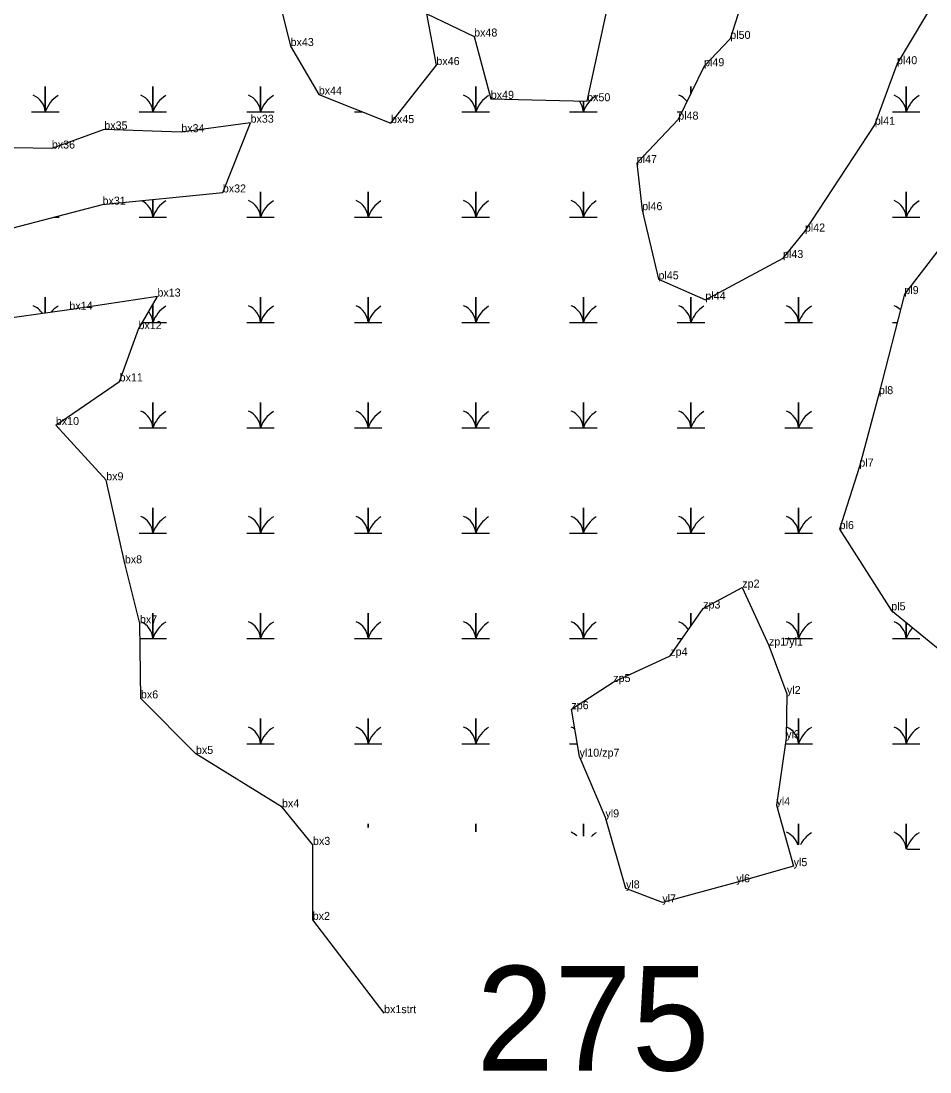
# Model space of a CAD drawing. Extents: x 2072529 to 2268796, y 436423 to 470406.
# Drawn here: x 2233706 to 2234274, y 437646 to 438303 of the extents above; entities that cross this region are included whole.
import ezdxf

# ---------------------------------------------------------------- set-up
doc = ezdxf.new("R2010")
doc.units = 0
for name, color, linetype in [('Default', 7, 'Continuous'), ('Exist Environmental Wetland Boundary', 7, 'Continuous'), ('Exist Environmental Wetland Boundary Cogo Comment', 7, 'Continuous'), ('Exist Hydro Swamp or Marsh', 7, 'Continuous'), ('Old_Level_20', 7, 'Continuous')]:
    doc.layers.add(name, color=color, linetype=linetype)

msp = doc.modelspace()

# ---------------------------------------------------------------- linework, layer by layer
at = {"layer": 'Exist Environmental Wetland Boundary'}
for points in [[(2234206.5, 438606.87), (2234215.25, 438571.96), (2234220.38, 438527.18), (2234204.32, 438480.7), (2234205.77, 438439.37), (2234198.43, 438402.89), (2234171.84, 438403.69), (2234163.55, 438367.07), (2234163.75, 438336.95), (2234149.39, 438291.75), (2234133.01, 438274.68), (2234116.86, 438241.33), (2234090.91, 438214.16), (2234094.32, 438184.72), (2234104.51, 438141.53), (2234133.82, 438128.75), (2234182.34, 438154.84), (2234196, 438171.36), (2234239.71, 438238.05), (2234253.57, 438275.93), (2234280.54, 438321.15)], [(2233858.66, 438351.45), (2233874.62, 438287.27), (2233892.26, 438257), (2233937.37, 438239.13), (2233965.72, 438275.42), (2233959.69, 438307.4), (2233989.31, 438293.23), (2233999.72, 438254.31), (2234059.94, 438252.78), (2234072.76, 438311.45)], [(2233677.19, 438167.39), (2233757.1, 438188.17), (2233832.28, 438195.79), (2233849.59, 438239.38), (2233806.32, 438233.44), (2233758.21, 438235.23), (2233725.42, 438223.22), (2233654.83, 438224.52)], [(2234279.17, 438159.32), (2234258.17, 438132.28), (2234242.26, 438069.78), (2234230.04, 438024.51), (2234217.72, 437985.47), (2234249.98, 437934.73), (2234302.96, 437891.47)], [(2233933.05, 437683.02), (2233888.45, 437741.29), (2233888.62, 437788.17), (2233869.26, 437811.67), (2233815.49, 437844.98), (2233781.11, 437879.68), (2233780.48, 437926.57), (2233771.05, 437964.06), (2233759.41, 438015.96), (2233727.92, 438050.47), (2233767.76, 438077.73), (2233779.58, 438110.39), (2233791.43, 438130.77), (2233736.36, 438122.5), (2233685.39, 438115.35)]]:
    msp.add_lwpolyline(points, dxfattribs=at)
msp.add_lwpolyline([(2234173.58, 437912.73), (2234184.81, 437882.46), (2234184.34, 437854.8), (2234178.23, 437812.94), (2234188.97, 437774.87), (2234153.16, 437764.75), (2234106.93, 437752.24), (2234084.22, 437760.95), (2234071.38, 437805.34), (2234055.2, 437843.29), (2234050.1, 437872.92), (2234076.23, 437889.9), (2234111.89, 437906.38), (2234132.43, 437935.84), (2234156.88, 437948.92)], close=True, dxfattribs=at)
at = {"layer": 'Exist Hydro Swamp or Marsh'}
for points in [[(2233712.73, 438246.13), (2233721.33, 438246.13), (2233721.33, 438261.91), (2233721.33, 438246.13), (2233729.93, 438246.13)], [(2233779.98, 438246.13), (2233788.58, 438246.13), (2233788.58, 438261.91), (2233788.58, 438246.13), (2233797.18, 438246.13)], [(2233847.23, 438246.13), (2233855.83, 438246.13), (2233855.83, 438261.91), (2233855.83, 438246.13), (2233864.43, 438246.13)], [(2233981.73, 438246.13), (2233990.33, 438246.13), (2233990.33, 438261.91), (2233990.33, 438246.13), (2233998.93, 438246.13)], [(2234124.83, 438257.79), (2234124.83, 438261.91), (2234124.83, 438257.79)], [(2234250.73, 438246.13), (2234259.33, 438246.13), (2234259.33, 438261.91), (2234259.33, 438246.13), (2234267.93, 438246.13)], [(2234048.98, 438246.13), (2234057.58, 438246.13), (2234057.58, 438252.84)], [(2234057.58, 438252.84), (2234057.58, 438246.13), (2234066.18, 438246.13)], [(2233914.48, 438246.13), (2233919.7, 438246.13)], [(2234116.23, 438246.13), (2234119.19, 438246.13)], [(2233847.23, 438180.33), (2233855.83, 438180.33), (2233855.83, 438196.11), (2233855.83, 438180.33), (2233864.43, 438180.33)], [(2233914.48, 438180.33), (2233923.08, 438180.33), (2233923.08, 438196.11), (2233923.08, 438180.33), (2233931.68, 438180.33)], [(2233981.73, 438180.33), (2233990.33, 438180.33), (2233990.33, 438196.11), (2233990.33, 438180.33), (2233998.93, 438180.33)], [(2234048.98, 438180.33), (2234057.58, 438180.33), (2234057.58, 438196.11), (2234057.58, 438180.33), (2234066.18, 438180.33)], [(2234250.73, 438180.33), (2234259.33, 438180.33), (2234259.33, 438196.11), (2234259.33, 438180.33), (2234267.93, 438180.33)], [(2233779.98, 438180.33), (2233788.58, 438180.33), (2233788.58, 438191.36)], [(2233788.58, 438191.36), (2233788.58, 438180.33), (2233797.18, 438180.33)], [(2233726.93, 438180.33), (2233729.93, 438180.33)], [(2233721.33, 438120.4), (2233721.33, 438130.31), (2233721.33, 438120.4)], [(2233847.23, 438114.53), (2233855.83, 438114.53), (2233855.83, 438130.31), (2233855.83, 438114.53), (2233864.43, 438114.53)], [(2233914.48, 438114.53), (2233923.08, 438114.53), (2233923.08, 438130.31), (2233923.08, 438114.53), (2233931.68, 438114.53)], [(2233981.73, 438114.53), (2233990.33, 438114.53), (2233990.33, 438130.31), (2233990.33, 438114.53), (2233998.93, 438114.53)], [(2234048.98, 438114.53), (2234057.58, 438114.53), (2234057.58, 438130.31), (2234057.58, 438114.53), (2234066.18, 438114.53)], [(2234116.23, 438114.53), (2234124.83, 438114.53), (2234124.83, 438130.31), (2234124.83, 438114.53), (2234133.43, 438114.53)], [(2234183.48, 438114.53), (2234192.08, 438114.53), (2234192.08, 438130.31), (2234192.08, 438114.53), (2234200.68, 438114.53)], [(2233781.99, 438114.53), (2233788.58, 438114.53), (2233788.58, 438125.87)], [(2233788.58, 438125.87), (2233788.58, 438114.53), (2233797.18, 438114.53)], [(2234250.73, 438114.53), (2234253.65, 438114.53)], [(2233779.98, 438048.73), (2233788.58, 438048.73), (2233788.58, 438064.51), (2233788.58, 438048.73), (2233797.18, 438048.73)], [(2233847.23, 438048.73), (2233855.83, 438048.73), (2233855.83, 438064.51), (2233855.83, 438048.73), (2233864.43, 438048.73)], [(2233914.48, 438048.73), (2233923.08, 438048.73), (2233923.08, 438064.51), (2233923.08, 438048.73), (2233931.68, 438048.73)], [(2233981.73, 438048.73), (2233990.33, 438048.73), (2233990.33, 438064.51), (2233990.33, 438048.73), (2233998.93, 438048.73)], [(2234048.98, 438048.73), (2234057.58, 438048.73), (2234057.58, 438064.51), (2234057.58, 438048.73), (2234066.18, 438048.73)], [(2234116.23, 438048.73), (2234124.83, 438048.73), (2234124.83, 438064.51), (2234124.83, 438048.73), (2234133.43, 438048.73)], [(2234183.48, 438048.73), (2234192.08, 438048.73), (2234192.08, 438064.51), (2234192.08, 438048.73), (2234200.68, 438048.73)], [(2233729.51, 438048.73), (2233729.93, 438048.73)], [(2233779.98, 437982.93), (2233788.58, 437982.93), (2233788.58, 437998.71), (2233788.58, 437982.93), (2233797.18, 437982.93)], [(2233847.23, 437982.93), (2233855.83, 437982.93), (2233855.83, 437998.71), (2233855.83, 437982.93), (2233864.43, 437982.93)], [(2233914.48, 437982.93), (2233923.08, 437982.93), (2233923.08, 437998.71), (2233923.08, 437982.93), (2233931.68, 437982.93)], [(2233981.73, 437982.93), (2233990.33, 437982.93), (2233990.33, 437998.71), (2233990.33, 437982.93), (2233998.93, 437982.93)], [(2234048.98, 437982.93), (2234057.58, 437982.93), (2234057.58, 437998.71), (2234057.58, 437982.93), (2234066.18, 437982.93)], [(2234116.23, 437982.93), (2234124.83, 437982.93), (2234124.83, 437998.71), (2234124.83, 437982.93), (2234133.43, 437982.93)], [(2234183.48, 437982.93), (2234192.08, 437982.93), (2234192.08, 437998.71), (2234192.08, 437982.93), (2234200.68, 437982.93)], [(2233780.61, 437917.13), (2233788.58, 437917.13), (2233788.58, 437932.91), (2233788.58, 437917.13), (2233797.18, 437917.13)], [(2233847.23, 437917.13), (2233855.83, 437917.13), (2233855.83, 437932.91), (2233855.83, 437917.13), (2233864.43, 437917.13)], [(2233914.48, 437917.13), (2233923.08, 437917.13), (2233923.08, 437932.91), (2233923.08, 437917.13), (2233931.68, 437917.13)], [(2233981.73, 437917.13), (2233990.33, 437917.13), (2233990.33, 437932.91), (2233990.33, 437917.13), (2233998.93, 437917.13)], [(2234048.98, 437917.13), (2234057.58, 437917.13), (2234057.58, 437932.91), (2234057.58, 437917.13), (2234066.18, 437917.13)], [(2234124.83, 437924.93), (2234124.83, 437932.91), (2234124.83, 437924.93)], [(2234183.48, 437917.13), (2234192.08, 437917.13), (2234192.08, 437932.91), (2234192.08, 437917.13), (2234200.68, 437917.13)], [(2234250.73, 437917.13), (2234259.33, 437917.13), (2234259.33, 437927.1)], [(2234259.33, 437927.1), (2234259.33, 437917.13), (2234267.93, 437917.13)], [(2234116.23, 437917.13), (2234119.39, 437917.13)], [(2233847.23, 437851.33), (2233855.83, 437851.33), (2233855.83, 437867.11), (2233855.83, 437851.33), (2233864.43, 437851.33)], [(2233914.48, 437851.33), (2233923.08, 437851.33), (2233923.08, 437867.11), (2233923.08, 437851.33), (2233931.68, 437851.33)], [(2233981.73, 437851.33), (2233990.33, 437851.33), (2233990.33, 437867.11), (2233990.33, 437851.33), (2233998.93, 437851.33)], [(2234183.84, 437851.33), (2234192.08, 437851.33), (2234192.08, 437867.11), (2234192.08, 437851.33), (2234200.68, 437851.33)], [(2234250.73, 437851.33), (2234259.33, 437851.33), (2234259.33, 437867.11), (2234259.33, 437851.33), (2234267.93, 437851.33)], [(2234048.98, 437851.33), (2234053.81, 437851.33)], [(2233923.08, 437799.12), (2233923.08, 437801.31), (2233923.08, 437799.12)], [(2233990.33, 437796.41), (2233990.33, 437801.31), (2233990.33, 437796.41)], [(2234057.58, 437793.69), (2234057.58, 437801.31), (2234057.58, 437793.69)], [(2234192.08, 437788.26), (2234192.08, 437801.31), (2234192.08, 437788.26)], [(2234259.33, 437785.55), (2234259.33, 437801.31), (2234259.33, 437785.55)], [(2234259.87, 437785.53), (2234267.93, 437785.53)]]:
    msp.add_lwpolyline(points, dxfattribs=at)
for centre, radius, start, end in [((2233709.06, 438245.24), 12.3, 4.14034, 67.53497), ((2233739.57, 438240.07), 19.22, 122.12745, 161.62219), ((2233776.31, 438245.24), 12.3, 4.14034, 67.53497), ((2233806.82, 438240.07), 19.22, 122.12745, 161.62219), ((2233843.56, 438245.24), 12.3, 4.14034, 67.53497), ((2233874.07, 438240.07), 19.22, 122.12745, 161.62219), ((2233978.06, 438245.24), 12.3, 4.14034, 67.53497), ((2234008.57, 438240.07), 19.22, 122.12745, 161.62219), ((2234075.82, 438240.07), 19.22, 122.12745, 161.62219), ((2234112.56, 438245.24), 12.3, 37.22159, 67.53497), ((2234247.06, 438245.24), 12.3, 4.14034, 67.53497), ((2234277.57, 438240.07), 19.22, 122.12745, 161.62219), ((2234045.31, 438245.24), 12.3, 4.14034, 38.57578), ((2233776.31, 438179.44), 12.3, 4.14034, 65.5639), ((2233806.82, 438174.27), 19.22, 122.12745, 161.62219), ((2233843.56, 438179.44), 12.3, 4.14034, 67.53497), ((2233874.07, 438174.27), 19.22, 122.12745, 161.62219), ((2233910.81, 438179.44), 12.3, 4.14034, 67.53497), ((2233941.32, 438174.27), 19.22, 122.12745, 161.62219), ((2233978.06, 438179.44), 12.3, 4.14034, 67.53497), ((2234008.57, 438174.27), 19.22, 122.12745, 161.62219), ((2234045.31, 438179.44), 12.3, 4.14034, 67.53497), ((2234075.82, 438174.27), 19.22, 122.12745, 161.62219), ((2234247.06, 438179.44), 12.3, 4.14034, 67.53497), ((2234277.57, 438174.27), 19.22, 122.12745, 161.62219), ((2233709.06, 438113.64), 12.3, 31.90656, 67.53497), ((2233739.57, 438108.47), 19.22, 122.12745, 139.70776), ((2233806.82, 438108.47), 19.22, 122.12745, 161.62219), ((2233843.56, 438113.64), 12.3, 4.14034, 67.53497), ((2233874.07, 438108.47), 19.22, 122.12745, 161.62219), ((2233910.81, 438113.64), 12.3, 4.14034, 67.53497), ((2233941.32, 438108.47), 19.22, 122.12745, 161.62219), ((2233978.06, 438113.64), 12.3, 4.14034, 67.53497), ((2234008.57, 438108.47), 19.22, 122.12745, 161.62219), ((2234045.31, 438113.64), 12.3, 4.14034, 67.53497), ((2234075.82, 438108.47), 19.22, 122.12745, 161.62219), ((2234112.56, 438113.64), 12.3, 4.14034, 67.53497), ((2234143.07, 438108.47), 19.22, 122.12745, 161.62219), ((2234179.81, 438113.64), 12.3, 4.14034, 67.53497), ((2234210.32, 438108.47), 19.22, 122.12745, 161.62219), ((2234247.06, 438113.64), 12.3, 45.63938, 67.53497), ((2233776.31, 438113.64), 12.3, 4.14034, 38.57705), ((2233776.31, 438047.84), 12.3, 4.14034, 67.53497), ((2233806.82, 438042.67), 19.22, 122.12745, 161.62219), ((2233843.56, 438047.84), 12.3, 4.14034, 67.53497), ((2233874.07, 438042.67), 19.22, 122.12745, 161.62219), ((2233910.81, 438047.84), 12.3, 4.14034, 67.53497), ((2233941.32, 438042.67), 19.22, 122.12745, 161.62219), ((2233978.06, 438047.84), 12.3, 4.14034, 67.53497), ((2234008.57, 438042.67), 19.22, 122.12745, 161.62219), ((2234045.31, 438047.84), 12.3, 4.14034, 67.53497), ((2234075.82, 438042.67), 19.22, 122.12745, 161.62219), ((2234112.56, 438047.84), 12.3, 4.14034, 67.53497), ((2234143.07, 438042.67), 19.22, 122.12745, 161.62219), ((2234179.81, 438047.84), 12.3, 4.14034, 67.53497), ((2234210.32, 438042.67), 19.22, 122.12745, 161.62219), ((2233776.31, 437982.04), 12.3, 4.14034, 67.53497), ((2233806.82, 437976.87), 19.22, 122.12745, 161.62219), ((2233843.56, 437982.04), 12.3, 4.14034, 67.53497), ((2233874.07, 437976.87), 19.22, 122.12745, 161.62219), ((2233910.81, 437982.04), 12.3, 4.14034, 67.53497), ((2233941.32, 437976.87), 19.22, 122.12745, 161.62219), ((2233978.06, 437982.04), 12.3, 4.14034, 67.53497), ((2234008.57, 437976.87), 19.22, 122.12745, 161.62219), ((2234045.31, 437982.04), 12.3, 4.14034, 67.53497), ((2234075.82, 437976.87), 19.22, 122.12745, 161.62219), ((2234112.56, 437982.04), 12.3, 4.14034, 67.53497), ((2234143.07, 437976.87), 19.22, 122.12745, 161.62219), ((2234179.81, 437982.04), 12.3, 4.14034, 67.53497), ((2234210.32, 437976.87), 19.22, 122.12745, 161.62219), ((2233776.31, 437916.24), 12.3, 4.14034, 67.53497), ((2233806.82, 437911.07), 19.22, 122.12745, 161.62219), ((2233843.56, 437916.24), 12.3, 4.14034, 67.53497), ((2233874.07, 437911.07), 19.22, 122.12745, 161.62219), ((2233910.81, 437916.24), 12.3, 4.14034, 67.53497), ((2233941.32, 437911.07), 19.22, 122.12745, 161.62219), ((2233978.06, 437916.24), 12.3, 4.14034, 67.53497), ((2234008.57, 437911.07), 19.22, 122.12745, 161.62219), ((2234045.31, 437916.24), 12.3, 4.14034, 67.53497), ((2234075.82, 437911.07), 19.22, 122.12745, 161.62219), ((2234112.56, 437916.24), 12.3, 30.66944, 67.53497), ((2234179.81, 437916.24), 12.3, 4.14034, 67.53497), ((2234210.32, 437911.07), 19.22, 122.12745, 161.62219), ((2234247.06, 437916.24), 12.3, 4.14034, 67.53497), ((2234277.57, 437911.07), 19.22, 138.1514, 161.62219), ((2233843.56, 437850.44), 12.3, 4.14034, 67.53497), ((2233874.07, 437845.27), 19.22, 122.12745, 161.62219), ((2233910.81, 437850.44), 12.3, 4.14034, 67.53497), ((2233941.32, 437845.27), 19.22, 122.12745, 161.62219), ((2233978.06, 437850.44), 12.3, 4.14034, 67.53497), ((2234008.57, 437845.27), 19.22, 122.12745, 161.62219), ((2234045.31, 437850.44), 12.3, 55.87281, 67.53497), ((2234179.81, 437850.44), 12.3, 4.14034, 67.53497), ((2234210.32, 437845.27), 19.22, 122.12745, 161.62219), ((2234247.06, 437850.44), 12.3, 4.14034, 67.53497), ((2234277.57, 437845.27), 19.22, 122.12745, 161.62219), ((2234045.31, 437784.64), 12.3, 48.56463, 67.53497), ((2234075.82, 437779.47), 19.22, 122.12745, 133.16556), ((2234179.81, 437784.64), 12.3, 17.24237, 67.53497), ((2234210.32, 437779.47), 19.22, 122.12745, 152.91763), ((2234247.06, 437784.64), 12.3, 4.24297, 67.53497), ((2234277.57, 437779.47), 19.22, 122.12745, 161.55428)]:
    msp.add_arc(centre, radius, start, end, dxfattribs=at)
at = {"layer": 'Old_Level_20'}
for p, q in [((2233989.31, 438293.23), (2233989.31, 438293.23)), ((2233874.62, 438287.27), (2233874.62, 438287.27)), ((2234149.39, 438291.75), (2234149.39, 438291.75)), ((2233965.72, 438275.42), (2233965.72, 438275.42)), ((2234133.01, 438274.68), (2234133.01, 438274.68)), ((2234253.57, 438275.93), (2234253.57, 438275.93)), ((2233892.26, 438257), (2233892.26, 438257)), ((2233999.72, 438254.31), (2233999.72, 438254.31)), ((2234059.94, 438252.78), (2234059.94, 438252.78)), ((2234116.86, 438241.33), (2234116.86, 438241.33)), ((2233758.21, 438235.23), (2233758.21, 438235.23)), ((2233849.59, 438239.38), (2233849.59, 438239.38)), ((2233937.37, 438239.13), (2233937.37, 438239.13)), ((2234239.71, 438238.05), (2234239.71, 438238.05)), ((2233806.32, 438233.44), (2233806.32, 438233.44)), ((2233725.42, 438223.22), (2233725.42, 438223.22)), ((2234090.91, 438214.16), (2234090.91, 438214.16)), ((2233832.28, 438195.79), (2233832.28, 438195.79)), ((2233757.1, 438188.17), (2233757.1, 438188.17)), ((2234094.32, 438184.72), (2234094.32, 438184.72)), ((2234196, 438171.36), (2234196, 438171.36)), ((2234182.34, 438154.84), (2234182.34, 438154.84)), ((2234104.51, 438141.53), (2234104.51, 438141.53)), ((2233791.43, 438130.77), (2233791.43, 438130.77)), ((2234133.82, 438128.75), (2234133.82, 438128.75)), ((2234258.17, 438132.28), (2234258.17, 438132.28)), ((2233736.36, 438122.5), (2233736.36, 438122.5)), ((2233779.58, 438110.39), (2233779.58, 438110.39)), ((2233767.76, 438077.73), (2233767.76, 438077.73)), ((2234242.26, 438069.78), (2234242.26, 438069.78)), ((2233727.92, 438050.47), (2233727.92, 438050.47)), ((2234230.04, 438024.51), (2234230.04, 438024.51)), ((2233759.41, 438015.96), (2233759.41, 438015.96)), ((2234217.72, 437985.47), (2234217.72, 437985.47)), ((2233771.05, 437964.06), (2233771.05, 437964.06)), ((2234156.88, 437948.92), (2234156.88, 437948.92)), ((2234132.43, 437935.84), (2234132.43, 437935.84)), ((2234249.98, 437934.73), (2234249.98, 437934.73)), ((2233780.48, 437926.57), (2233780.48, 437926.57)), ((2234173.58, 437912.73), (2234173.58, 437912.73)), ((2234111.89, 437906.38), (2234111.89, 437906.38)), ((2234076.23, 437889.9), (2234076.23, 437889.9)), ((2233781.11, 437879.68), (2233781.11, 437879.68)), ((2234184.81, 437882.46), (2234184.81, 437882.46)), ((2234050.1, 437872.92), (2234050.1, 437872.92)), ((2234184.34, 437854.8), (2234184.34, 437854.8)), ((2233815.49, 437844.98), (2233815.49, 437844.98)), ((2234055.2, 437843.29), (2234055.2, 437843.29)), ((2233869.26, 437811.67), (2233869.26, 437811.67)), ((2234178.23, 437812.94), (2234178.23, 437812.94)), ((2234071.38, 437805.34), (2234071.38, 437805.34)), ((2233888.62, 437788.17), (2233888.62, 437788.17)), ((2234188.97, 437774.87), (2234188.97, 437774.87)), ((2234084.22, 437760.95), (2234084.22, 437760.95)), ((2234153.16, 437764.75), (2234153.16, 437764.75)), ((2234106.93, 437752.24), (2234106.93, 437752.24)), ((2233888.45, 437741.29), (2233888.45, 437741.29)), ((2233933.05, 437683.02), (2233933.05, 437683.02))]:
    msp.add_line(p, q, dxfattribs=at)

# ---------------------------------------------------------------- texts
at = {"layer": 'Default'}
msp.add_text('275', height=65.34, dxfattribs=at).set_placement((2233990.69, 437647.19))
at = {"layer": 'Exist Environmental Wetland Boundary Cogo Comment'}
for s, p in [('bx48', (2233989.31, 438293.23)), ('pl50', (2234149.39, 438291.75)), ('bx43', (2233874.62, 438287.27)), ('bx46', (2233965.72, 438275.42)), ('pl49', (2234133.01, 438274.68)), ('pl40', (2234253.57, 438275.93)), ('bx44', (2233892.26, 438257)), ('bx49', (2233999.72, 438254.31)), ('bx50', (2234059.94, 438252.78)), ('pl48', (2234116.86, 438241.33)), ('bx35', (2233758.21, 438235.23)), ('bx33', (2233849.59, 438239.38)), ('bx45', (2233937.37, 438239.13)), ('pl41', (2234239.71, 438238.05)), ('bx34', (2233806.32, 438233.44)), ('bx36', (2233725.42, 438223.22)), ('pl47', (2234090.91, 438214.16)), ('bx32', (2233832.28, 438195.79)), ('bx31', (2233757.1, 438188.17)), ('pl46', (2234094.32, 438184.72)), ('pl42', (2234196, 438171.36)), ('pl43', (2234182.34, 438154.84)), ('pl45', (2234104.51, 438141.53)), ('bx13', (2233791.43, 438130.77)), ('pl9', (2234258.17, 438132.28)), ('pl44', (2234133.82, 438128.75)), ('bx14', (2233736.36, 438122.5)), ('bx12', (2233779.58, 438110.39)), ('bx11', (2233767.76, 438077.73)), ('pl8', (2234242.26, 438069.78)), ('bx10', (2233727.92, 438050.47)), ('pl7', (2234230.04, 438024.51)), ('bx9', (2233759.41, 438015.96)), ('pl6', (2234217.72, 437985.47)), ('bx8', (2233771.05, 437964.06)), ('zp2', (2234156.88, 437948.92)), ('zp3', (2234132.43, 437935.84)), ('pl5', (2234249.98, 437934.73)), ('bx7', (2233780.48, 437926.57)), ('zp1/yl1', (2234173.58, 437912.73)), ('zp4', (2234111.89, 437906.38)), ('zp5', (2234076.23, 437889.9)), ('yl2', (2234184.81, 437882.46)), ('bx6', (2233781.11, 437879.68)), ('zp6', (2234050.1, 437872.92)), ('yl3', (2234184.34, 437854.8)), ('bx5', (2233815.49, 437844.98)), ('yl10/zp7', (2234055.2, 437843.29)), ('bx4', (2233869.26, 437811.67)), ('yl4', (2234178.23, 437812.94)), ('yl9', (2234071.38, 437805.34)), ('bx3', (2233888.62, 437788.17)), ('yl5', (2234188.97, 437774.87)), ('yl6', (2234153.16, 437764.75)), ('yl8', (2234084.22, 437760.95)), ('yl7', (2234106.93, 437752.24)), ('bx2', (2233888.45, 437741.29)), ('bx1strt', (2233933.05, 437683.02))]:
    msp.add_text(s, height=5, dxfattribs=at).set_placement(p)

doc.saveas('drawing.dxf')
